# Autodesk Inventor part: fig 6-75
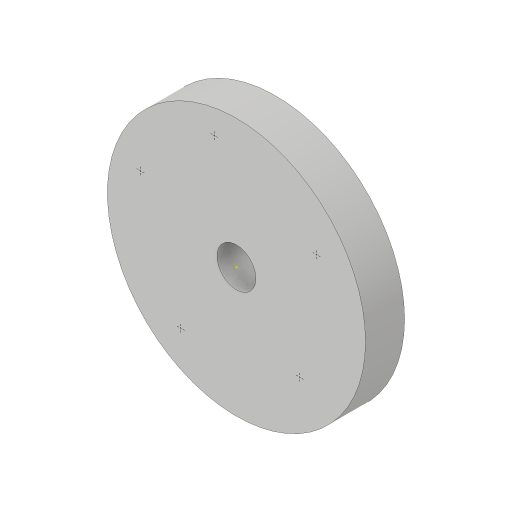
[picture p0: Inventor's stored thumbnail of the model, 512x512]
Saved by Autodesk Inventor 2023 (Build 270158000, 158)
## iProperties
Created: 2018-03
Part Number: fig 6-75
Material: Generic
Document SubType Name: Modeling
Designer: CADCIM 00
Density: 1 g/cm^3
Appearance: Default
Author: CADCIM 00
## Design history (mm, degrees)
sketch "Sketch1"
  geometry: C1 r 16.506 at (0, 0); 1 further point
  constraints: 1 centre point, 1 coincident
extrude "Extrusion1" new body sketch "Sketch1" distance "d0" = 5; taper "d1" = 0 deg
sketch "Sketch3"
  geometry: 2 further points
  constraints: 1 coincident
hole "Hole1" sketch "Sketch3" at (0, 0) diameter "d2" = 5; stored, may be unused: countersink angle "d6" = 90 deg, drill point angle "d8" = 118 deg; dims "d3" = 6, "d4" = 4, "d5" = 2, "d7" = 8
sketch "Sketch2"
  geometry: 6 further points
body "Solid1"
